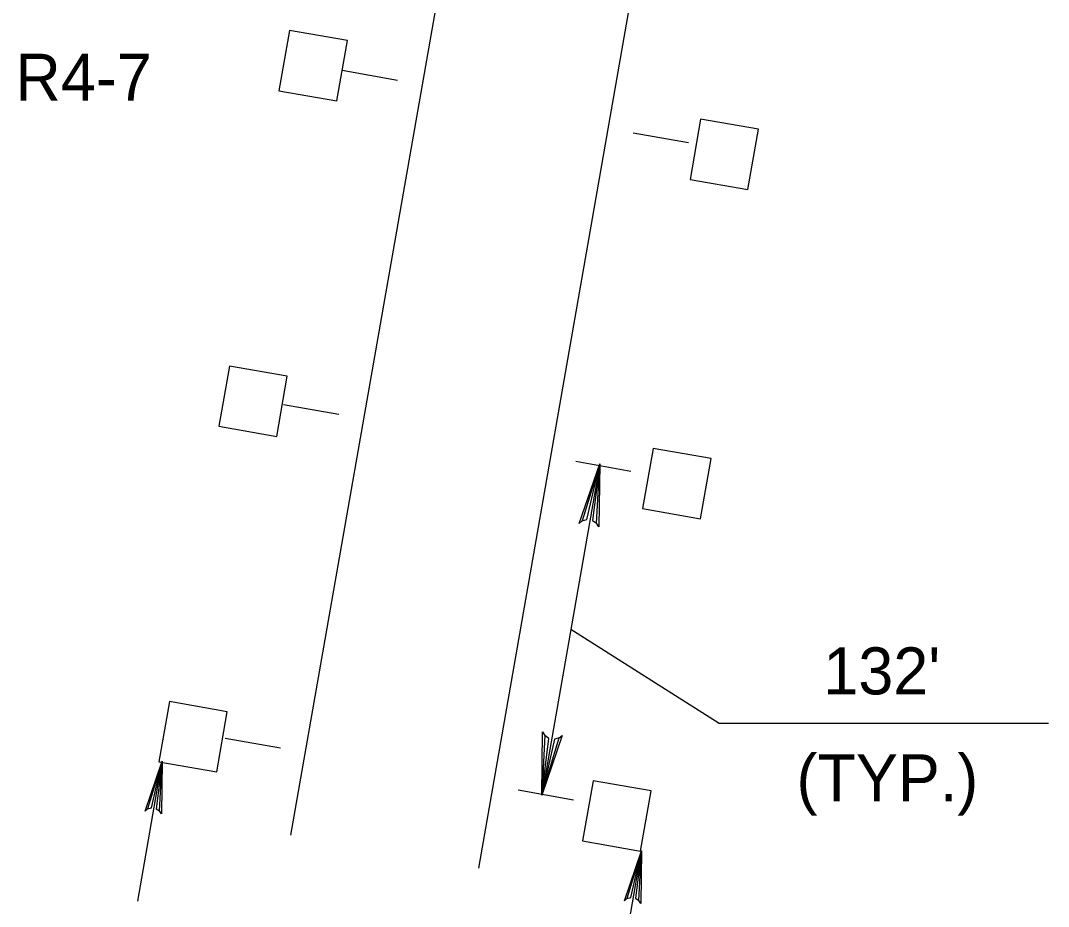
# Model space of a CAD drawing. Extents: x 640253 to 641999, y 298458 to 299646.
# Drawn here: x 641531.2 to 641596.7, y 299250.5 to 299307 of the extents above; entities that cross this region are included whole.
import ezdxf

# ---------------------------------------------------------------- set-up
doc = ezdxf.new("R2010")
doc.units = 0
doc.layers.add('2', color=7, linetype='Continuous')

msp = doc.modelspace()

# ---------------------------------------------------------------- linework, layer by layer
at = {"layer": '2'}
for p, q in [((641548.404, 299255.062), (641564.233, 299345.458)), ((641560.381, 299252.962), (641575.95, 299342.02)), ((641555.19, 299303.177), (641551.667, 299303.802)), ((641555.19, 299303.177), (641555.19, 299303.177)), ((641570.221, 299299.843), (641570.221, 299299.843)), ((641570.221, 299299.843), (641573.746, 299299.218)), ((641551.459, 299281.879), (641547.936, 299282.504)), ((641551.459, 299281.879), (641551.459, 299281.879)), ((641566.561, 299278.893), (641566.561, 299278.893)), ((641566.561, 299278.893), (641570.084, 299278.268)), ((641568.088, 299278.737), (641564.39, 299257.614)), ((641575.718, 299262.186), (641566.239, 299268.175)), ((641547.727, 299260.599), (641544.204, 299261.224)), ((641547.727, 299260.599), (641547.727, 299260.599)), ((641538.631, 299250.843), (641540.194, 299259.766)), ((641562.898, 299257.943), (641562.898, 299257.943)), ((641562.898, 299257.943), (641566.421, 299257.318)), ((641569.198, 299245.133), (641570.76, 299254.056)), ((641560.381, 299252.962), (641560.381, 299252.962))]:
    msp.add_line(p, q, dxfattribs=at)
for points in [[(641551.329, 299301.874), (641552, 299305.714), (641548.309, 299306.36), (641547.638, 299302.52)], [(641577.546, 299296.222), (641578.217, 299300.062), (641574.525, 299300.708), (641573.854, 299296.868)], [(641547.498, 299280.481), (641548.169, 299284.32), (641544.477, 299284.966), (641543.806, 299281.127)], [(641574.521, 299275.235), (641575.192, 299279.074), (641571.5, 299279.72), (641570.829, 299275.881)], [(641543.667, 299259.089), (641544.338, 299262.929), (641540.646, 299263.574), (641539.975, 299259.735)], [(641570.69, 299254.043), (641571.361, 299257.883), (641567.669, 299258.529), (641566.998, 299254.689)]]:
    msp.add_lwpolyline(points, close=True, dxfattribs=at)
for points in [[(641566.967, 299275.091), (641567.26, 299275.183), (641568.088, 299278.737), (641566.967, 299275.091), (641566.771, 299274.929), (641568.088, 299278.737), (641567.638, 299275.12), (641567.881, 299274.943), (641568.088, 299278.737), (641568.025, 299274.71), (641567.881, 299274.943)], [(641596.705, 299262.186), (641575.718, 299262.186)], [(641565.51, 299261.26), (641565.217, 299261.168), (641564.39, 299257.614), (641565.51, 299261.26), (641565.706, 299261.422), (641564.39, 299257.614), (641564.84, 299261.231), (641564.596, 299261.408), (641564.39, 299257.614), (641564.452, 299261.641), (641564.596, 299261.408)], [(641539.256, 299256.729), (641539.5, 299256.797), (641540.194, 299259.766), (641539.256, 299256.729), (641539.1, 299256.589), (641540.194, 299259.766), (641539.813, 299256.745), (641540.021, 299256.608), (641540.194, 299259.766), (641540.142, 299256.416), (641540.021, 299256.608)], [(641569.823, 299251.018), (641570.065, 299251.087), (641570.76, 299254.056), (641569.823, 299251.018), (641569.667, 299250.879), (641570.76, 299254.056), (641570.377, 299251.035), (641570.586, 299250.895), (641570.76, 299254.056), (641570.709, 299250.706), (641570.586, 299250.895)]]:
    msp.add_lwpolyline(points, dxfattribs=at)

# ---------------------------------------------------------------- texts
for s, p in [('R4-7', (641530.829, 299301.878)), ("132'", (641582.351, 299264.032)), ('(TYP.)', (641580.64, 299257.21))]:
    msp.add_text(s, height=3, dxfattribs=at).set_placement(p)

doc.saveas('drawing.dxf')
